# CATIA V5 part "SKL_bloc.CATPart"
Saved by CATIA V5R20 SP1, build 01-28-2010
Part number: SKL_bloc
Publications: "Plan_de_refSKL"
Bounding box of the stored display mesh (mm): x -85 to 85, y -60.104 to 60.104, z 0 to 0
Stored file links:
  C:\Users\Nikow\Documents\IAO\Mécanisme IAO avec squelette\SKL_bloc.CATPart
  C:\Users\Nikow\Documents\IAO\Mécanisme IAO avec squelette\Mecanisme_a_bielle_et_deux_coulisseaux.CATProduct
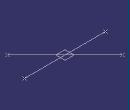
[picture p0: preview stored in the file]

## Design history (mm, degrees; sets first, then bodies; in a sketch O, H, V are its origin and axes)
Set1
  Point1 to Point4: linked copy from another document
  Plane1 "Plan_de_ref": linked copy from another document
Body1 (main body)
  Line1: type PtPt, FirstPoint Point1, SecondPoint Point2
  Line2: type PtPt, FirstPoint Point3, SecondPoint Point4
  Point5 "Point.1": type OnPlane, Support Plane1, RefPoint Point1, H 0, V 0, Direction (1, 0, 0)
  Point6 "Point.2": type OnPlane, Support Plane1, RefPoint Point2, H 0, V 0, Direction (1, 0, 0)
  Point7 "Point.3": type OnPlane, Support Plane1, RefPoint Point3, H 0, V 0, Direction (1, 0, 0)
  Point8 "Point.4": type OnPlane, Support Plane1, RefPoint Point4, H 0, V 0, Direction (1, 0, 0)
  Plane2 "Plan_de_refSKL": type Offset, RefPlane Plane1, Offset 0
